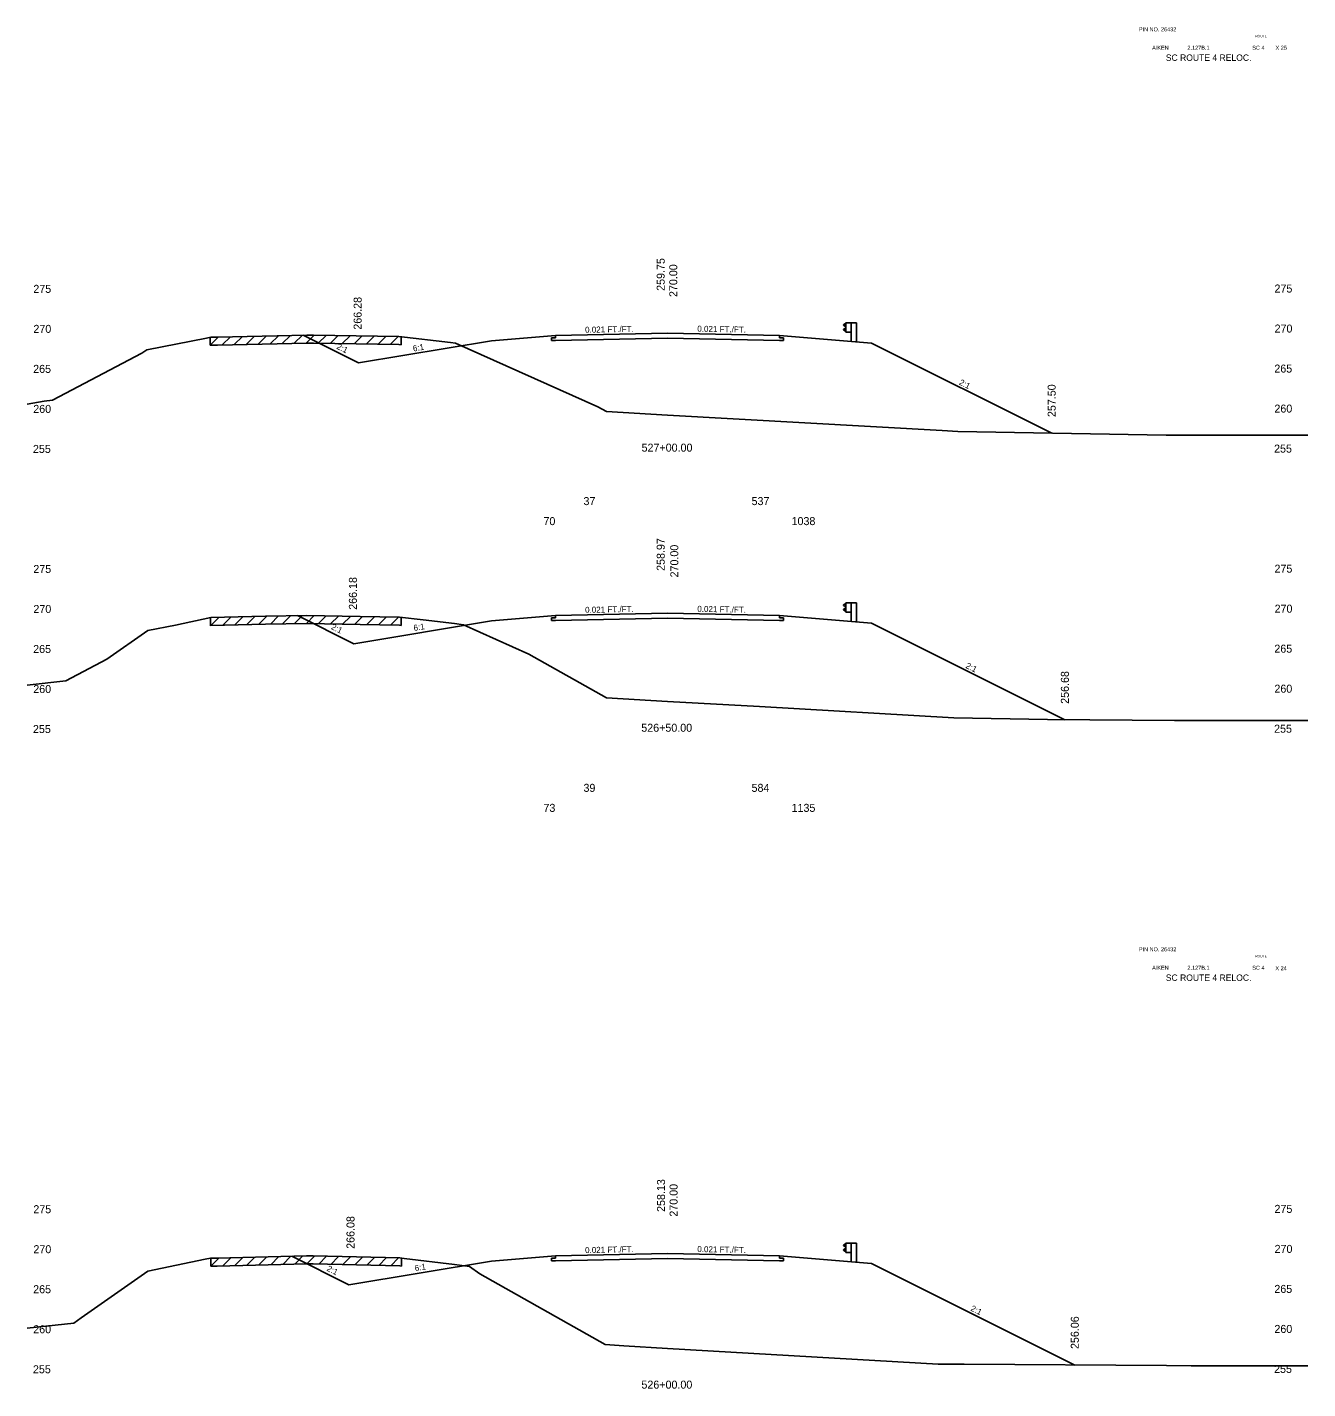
# Model space of a CAD drawing. Extents: x 2967 to 4323, y -3677 to -817.
# Drawn here: x 3188.8 to 3348.8, y -986.8 to -816.6 of the extents above; entities that cross this region are included whole.
import ezdxf

# ---------------------------------------------------------------- set-up
doc = ezdxf.new("R2010")
doc.units = 0
for name, color, linetype in [('Level 1', 7, 'Continuous'), ('Level 10', 7, 'Continuous'), ('Level 11', 7, 'Continuous'), ('Level 12', 7, 'Continuous'), ('Level 20', 7, 'Continuous'), ('Level 24', 7, 'Continuous'), ('Level 3', 7, 'Continuous'), ('Level 32', 7, 'Continuous'), ('Level 33', 7, 'Continuous'), ('Level 59', 7, 'Continuous'), ('Level 6', 7, 'Continuous'), ('Level 60', 7, 'Continuous'), ('Level 61', 7, 'Continuous'), ('Level 7', 7, 'Continuous')]:
    doc.layers.add(name, color=color, linetype=linetype)

msp = doc.modelspace()

# ---------------------------------------------------------------- linework, layer by layer
at = {"layer": 'Level 11'}
for p, q in [((3254.76, -855.43), (3254.26, -855.44)), ((3254.26, -855.44), (3254.26, -855.78)), ((3254.76, -855.13), (3254.76, -855.43)), ((3282.76, -855.43), (3282.76, -855.13)), ((3283.26, -855.44), (3282.76, -855.43)), ((3283.26, -855.78), (3283.26, -855.44)), ((3254.26, -855.78), (3254.76, -855.77)), ((3282.76, -855.77), (3283.26, -855.78)), ((3254.76, -890.43), (3254.26, -890.44)), ((3254.26, -890.44), (3254.26, -890.78)), ((3254.26, -890.78), (3254.76, -890.77)), ((3254.76, -890.13), (3254.76, -890.43)), ((3282.76, -890.43), (3282.76, -890.13)), ((3283.26, -890.44), (3282.76, -890.43)), ((3282.76, -890.77), (3283.26, -890.78)), ((3283.26, -890.78), (3283.26, -890.44)), ((3254.76, -970.43), (3254.26, -970.44)), ((3254.26, -970.44), (3254.26, -970.78)), ((3254.26, -970.78), (3254.76, -970.77)), ((3254.76, -970.13), (3254.76, -970.43)), ((3282.76, -970.43), (3282.76, -970.13)), ((3283.26, -970.44), (3282.76, -970.43)), ((3282.76, -970.77), (3283.26, -970.78)), ((3283.26, -970.78), (3283.26, -970.44))]:
    msp.add_line(p, q, dxfattribs=at)
at = {"layer": 'Level 12'}
for p, q in [((3268.76, -855.48), (3254.76, -855.77)), ((3282.76, -855.77), (3268.76, -855.48)), ((3268.76, -890.48), (3254.76, -890.77)), ((3282.76, -890.77), (3268.76, -890.48)), ((3268.76, -970.48), (3254.76, -970.77)), ((3282.76, -970.77), (3268.76, -970.48))]:
    msp.add_line(p, q, dxfattribs=at)
at = {"layer": 'Level 24'}
for p, q in [((3291.03, -853.62), (3290.76, -853.82)), ((3290.76, -853.82), (3290.76, -853.87)), ((3290.76, -853.87), (3291.03, -854.07)), ((3291.03, -854.72), (3291.03, -853.55)), ((3291.03, -853.55), (3291.7, -853.55)), ((3291.7, -853.55), (3291.7, -855.88)), ((3291.7, -853.55), (3292.36, -853.55)), ((3292.36, -853.55), (3292.36, -855.93)), ((3290.76, -854.39), (3291.03, -854.19)), ((3290.76, -854.44), (3290.76, -854.39)), ((3291.03, -854.64), (3290.76, -854.44)), ((3291.03, -854.72), (3291.7, -854.72)), ((3291.03, -888.62), (3290.76, -888.82)), ((3290.76, -888.82), (3290.76, -888.87)), ((3290.76, -888.87), (3291.03, -889.07)), ((3290.76, -889.39), (3291.03, -889.19)), ((3290.76, -889.44), (3290.76, -889.39)), ((3291.03, -889.64), (3290.76, -889.44)), ((3291.03, -889.72), (3291.03, -888.55)), ((3291.03, -888.55), (3291.7, -888.55)), ((3291.03, -889.72), (3291.7, -889.72)), ((3291.7, -888.55), (3291.7, -890.88)), ((3291.7, -888.55), (3292.36, -888.55)), ((3292.36, -888.55), (3292.36, -890.93)), ((3291.03, -968.62), (3290.76, -968.82)), ((3290.76, -968.82), (3290.76, -968.87)), ((3290.76, -968.87), (3291.03, -969.07)), ((3290.76, -969.39), (3291.03, -969.19)), ((3290.76, -969.44), (3290.76, -969.39)), ((3291.03, -969.64), (3290.76, -969.44)), ((3291.03, -969.72), (3291.03, -968.55)), ((3291.03, -968.55), (3291.7, -968.55)), ((3291.03, -969.72), (3291.7, -969.72)), ((3291.7, -968.55), (3291.7, -970.88)), ((3291.7, -968.55), (3292.36, -968.55)), ((3292.36, -968.55), (3292.36, -970.93))]:
    msp.add_line(p, q, dxfattribs=at)
at = {"layer": 'Level 59'}
for p, q in [((3254.76, -855.13), (3268.76, -854.84)), ((3268.76, -854.84), (3282.76, -855.13)), ((3254.76, -890.13), (3268.76, -889.84)), ((3268.76, -889.84), (3282.76, -890.13)), ((3254.76, -970.13), (3268.76, -969.84)), ((3268.76, -969.84), (3282.76, -970.13))]:
    msp.add_line(p, q, dxfattribs=at)
at = {"layer": 'Level 6'}
for p, q in [((3246.76, -855.8), (3254.76, -855.13)), ((3282.76, -855.13), (3290.76, -855.8)), ((3290.76, -855.8), (3294.26, -856.09)), ((3246.76, -890.8), (3254.76, -890.13)), ((3282.76, -890.13), (3290.76, -890.8)), ((3290.76, -890.8), (3294.26, -891.09)), ((3246.76, -970.8), (3254.76, -970.13)), ((3282.76, -970.13), (3290.76, -970.8)), ((3290.76, -970.8), (3294.26, -971.09))]:
    msp.add_line(p, q, dxfattribs=at)
at = {"layer": 'Level 60'}
for p, q in [((3203.69, -856.93), (3211.15, -855.47)), ((3211.15, -855.47), (3211.69, -855.36)), ((3211.69, -855.36), (3212.52, -855.34)), ((3212.52, -855.34), (3223.69, -855.09)), ((3223.69, -855.09), (3224.52, -855.1)), ((3224.52, -855.1), (3235.19, -855.28)), ((3235.19, -855.28), (3241.66, -856.02)), ((3191.9, -863.23), (3203.07, -857.37)), ((3203.07, -857.37), (3203.69, -856.93)), ((3241.66, -856.02), (3242.27, -856.09)), ((3242.27, -856.09), (3260.06, -864.06)), ((3188.76, -863.71), (3190.86, -863.35)), ((3190.86, -863.35), (3191.9, -863.23)), ((3260.06, -864.06), (3261.12, -864.66)), ((3261.12, -864.66), (3268.76, -865.09)), ((3268.76, -865.09), (3303.06, -867.02)), ((3303.06, -867.02), (3305.04, -867.13)), ((3305.04, -867.13), (3331.06, -867.6)), ((3331.06, -867.6), (3332.07, -867.61)), ((3332.07, -867.61), (3332.8, -867.61)), ((3332.8, -867.61), (3348.76, -867.6)), ((3203.84, -892), (3207.28, -891.33)), ((3207.28, -891.33), (3211.68, -890.4)), ((3211.68, -890.4), (3218.51, -890.23)), ((3218.51, -890.23), (3223.66, -890.12)), ((3223.66, -890.12), (3230.36, -890.27)), ((3230.36, -890.27), (3235.26, -890.35)), ((3235.26, -890.35), (3238.23, -890.68)), ((3238.23, -890.68), (3242.13, -891.14)), ((3242.13, -891.14), (3243.27, -891.31)), ((3243.27, -891.31), (3251.43, -894.97)), ((3198.69, -895.61), (3203.84, -892)), ((3193.57, -898.3), (3198.69, -895.61)), ((3251.43, -894.97), (3261.12, -900.44)), ((3188.76, -898.85), (3193.57, -898.3)), ((3261.12, -900.44), (3268.76, -900.87)), ((3268.76, -900.87), (3280.25, -901.52)), ((3280.25, -901.52), (3304.53, -902.94)), ((3304.53, -902.94), (3316.25, -903.15)), ((3316.25, -903.15), (3332.09, -903.27)), ((3332.09, -903.27), (3343.53, -903.27)), ((3343.53, -903.27), (3348.76, -903.27)), ((3203.82, -972.08), (3211.01, -970.57)), ((3211.01, -970.57), (3211.67, -970.44)), ((3211.67, -970.44), (3212.49, -970.42)), ((3212.49, -970.42), (3223.65, -970.14)), ((3223.65, -970.14), (3224.47, -970.16)), ((3224.47, -970.16), (3235.32, -970.41)), ((3235.32, -970.41), (3235.86, -970.48)), ((3235.86, -970.48), (3242.16, -971.22)), ((3242.16, -971.22), (3244.01, -971.5)), ((3195.51, -977.91), (3203.82, -972.08)), ((3244.01, -971.5), (3245.32, -972.38)), ((3245.32, -972.38), (3260.99, -981.24)), ((3194.6, -978.54), (3195.51, -977.91)), ((3188.76, -979.2), (3194.6, -978.54)), ((3260.99, -981.24), (3263.31, -981.39)), ((3263.31, -981.39), (3268.76, -981.71)), ((3268.76, -981.71), (3302.58, -983.69)), ((3302.58, -983.69), (3305.84, -983.68)), ((3305.84, -983.68), (3331.12, -983.87)), ((3331.12, -983.87), (3334.19, -983.89)), ((3334.19, -983.89), (3348.76, -983.89))]:
    msp.add_line(p, q, dxfattribs=at)
at = {"layer": 'Level 61'}
for p, q in [((3212.65, -855.33), (3211.61, -856.37)), ((3211.61, -855.37), (3211.61, -856.37)), ((3214.14, -855.3), (3213.11, -856.32)), ((3215.64, -855.27), (3214.61, -856.29)), ((3217.14, -855.23), (3216.11, -856.26)), ((3218.64, -855.2), (3217.61, -856.22)), ((3220.14, -855.17), (3219.11, -856.19)), ((3221.64, -855.13), (3220.61, -856.16)), ((3223.14, -855.1), (3222.11, -856.12)), ((3224.59, -855.11), (3223.61, -856.09)), ((3226.1, -855.13), (3225.11, -856.11)), ((3227.6, -855.16), (3226.61, -856.14)), ((3229.1, -855.18), (3228.11, -856.16)), ((3230.6, -855.21), (3229.61, -856.19)), ((3232.1, -855.23), (3231.11, -856.21)), ((3233.6, -855.25), (3232.61, -856.24)), ((3235.1, -855.28), (3234.11, -856.26)), ((3235.46, -856.31), (3235.46, -855.31)), ((3211.61, -856.37), (3211.69, -856.36)), ((3211.69, -856.36), (3212.52, -856.34)), ((3212.52, -856.34), (3223.69, -856.09)), ((3223.69, -856.09), (3224.52, -856.1)), ((3224.52, -856.1), (3235.19, -856.28)), ((3235.19, -856.28), (3235.46, -856.31)), ((3212.68, -890.38), (3211.65, -891.41)), ((3211.65, -890.41), (3211.65, -891.41)), ((3211.65, -891.41), (3211.68, -891.4)), ((3211.68, -891.4), (3218.51, -891.23)), ((3214.18, -890.34), (3213.15, -891.37)), ((3215.68, -890.3), (3214.65, -891.33)), ((3217.18, -890.27), (3216.15, -891.29)), ((3218.68, -890.23), (3217.65, -891.25)), ((3218.51, -891.23), (3223.66, -891.12)), ((3220.17, -890.19), (3219.15, -891.22)), ((3221.67, -890.16), (3220.65, -891.18)), ((3223.17, -890.13), (3222.15, -891.15)), ((3224.63, -890.14), (3223.65, -891.12)), ((3223.66, -891.12), (3230.36, -891.27)), ((3226.13, -890.17), (3225.15, -891.15)), ((3227.63, -890.2), (3226.65, -891.18)), ((3229.13, -890.24), (3228.15, -891.22)), ((3230.63, -890.27), (3229.65, -891.25)), ((3230.36, -891.27), (3235.26, -891.35)), ((3232.13, -890.29), (3231.15, -891.28)), ((3233.63, -890.32), (3232.65, -891.3)), ((3235.13, -890.34), (3234.15, -891.33)), ((3235.26, -891.35), (3235.5, -891.37)), ((3235.5, -891.37), (3235.5, -890.37)), ((3212.71, -970.42), (3211.69, -971.44)), ((3211.69, -970.44), (3211.69, -971.44)), ((3211.69, -971.44), (3212.49, -971.42)), ((3212.49, -971.42), (3223.65, -971.14)), ((3214.21, -970.38), (3213.19, -971.41)), ((3215.71, -970.34), (3214.69, -971.37)), ((3217.21, -970.31), (3216.19, -971.33)), ((3218.71, -970.27), (3217.69, -971.29)), ((3220.21, -970.23), (3219.19, -971.26)), ((3221.71, -970.19), (3220.69, -971.22)), ((3223.21, -970.15), (3222.19, -971.18)), ((3223.65, -971.14), (3224.47, -971.16)), ((3224.66, -970.17), (3223.69, -971.14)), ((3224.47, -971.16), (3235.32, -971.41)), ((3226.16, -970.2), (3225.19, -971.18)), ((3227.66, -970.24), (3226.69, -971.21)), ((3229.16, -970.27), (3228.19, -971.25)), ((3230.66, -970.3), (3229.69, -971.28)), ((3232.16, -970.34), (3231.19, -971.31)), ((3233.66, -970.37), (3232.69, -971.35)), ((3235.16, -970.4), (3234.19, -971.38)), ((3235.32, -971.41), (3235.53, -971.44)), ((3235.53, -971.44), (3235.53, -970.44))]:
    msp.add_line(p, q, dxfattribs=at)
at = {"layer": 'Level 7'}
for p, q in [((3223.22, -855.1), (3230.16, -858.57)), ((3230.16, -858.57), (3246.76, -855.8)), ((3294.26, -856.09), (3316.76, -867.34)), ((3222.51, -890.14), (3229.56, -893.67)), ((3229.56, -893.67), (3246.76, -890.8)), ((3294.26, -891.09), (3318.41, -903.17)), ((3221.81, -970.19), (3228.96, -973.77)), ((3228.96, -973.77), (3246.76, -970.8)), ((3294.26, -971.09), (3319.65, -983.79))]:
    msp.add_line(p, q, dxfattribs=at)

# ---------------------------------------------------------------- texts
at = {"layer": 'Level 1'}
for s, p in [('37', (3258.26, -876.34)), ('537', (3279.26, -876.34)), ('70', (3253.26, -878.84)), ('1038', (3284.26, -878.84)), ('39', (3258.26, -912.17)), ('584', (3279.26, -912.17)), ('73', (3253.26, -914.67)), ('1135', (3284.26, -914.67))]:
    msp.add_text(s, height=1, dxfattribs=at).set_placement(p)
at = {"layer": 'Level 10'}
for s, p in [('259.75', (3268.41, -849.57)), ('258.97', (3268.41, -884.56)), ('258.13', (3268.45, -964.66))]:
    msp.add_text(s, height=1, rotation=90, dxfattribs=at).set_placement(p)
for s, p in [('527+00.00', (3265.52, -869.66)), ('526+50.00', (3265.48, -904.66)), ('526+00.00', (3265.5, -986.74))]:
    msp.add_text(s, height=1, dxfattribs=at).set_placement(p)
at = {"layer": 'Level 20'}
for s, height, p in [('PIN NO. 26432', 0.5, (3327.65, -817.14)), ('ROUTE', 0.3, (3342.19, -817.88)), ('AIKEN', 0.5, (3329.31, -819.44)), ('SC ROUTE 4 RELOC.', 0.8, (3331.02, -820.83)), (' 2.127B.1', 0.5, (3333.53, -819.44)), ('SC 4', 0.5, (3341.82, -819.44)), ('X 25', 0.5, (3344.73, -819.44)), ('PIN NO. 26432', 0.5, (3327.65, -932.09)), ('AIKEN', 0.5, (3329.31, -934.4)), (' 2.127B.1', 0.5, (3333.53, -934.4)), ('SC 4', 0.5, (3341.82, -934.4)), ('ROUTE', 0.3, (3342.19, -932.84)), ('X 24', 0.5, (3344.71, -934.46)), ('SC ROUTE 4 RELOC.', 0.8, (3331.02, -935.79))]:
    msp.add_text(s, height=height, dxfattribs=at).set_placement(p)
at = {"layer": 'Level 3'}
for s, p in [(' 275', (3189.15, -849.82)), (' 275', (3344.23, -849.78)), (' 270', (3189.16, -854.82)), (' 270', (3344.24, -854.78)), (' 265', (3189.13, -859.82)), (' 265', (3344.21, -859.78)), (' 260', (3189.14, -864.82)), (' 260', (3344.22, -864.78)), (' 255', (3189.1, -869.82)), (' 255', (3344.18, -869.78)), (' 275', (3189.15, -884.82)), (' 275', (3344.23, -884.78)), (' 270', (3189.16, -889.82)), (' 270', (3344.24, -889.78)), (' 265', (3189.13, -894.82)), (' 265', (3344.21, -894.78)), (' 260', (3189.14, -899.82)), (' 260', (3344.22, -899.78)), (' 255', (3189.1, -904.82)), (' 255', (3344.18, -904.78)), (' 275', (3189.15, -964.82)), (' 275', (3344.23, -964.78)), (' 270', (3189.16, -969.82)), (' 270', (3344.24, -969.78)), (' 265', (3189.13, -974.82)), (' 265', (3344.21, -974.78)), (' 260', (3189.14, -979.82)), (' 260', (3344.22, -979.78)), (' 255', (3189.1, -984.82)), (' 255', (3344.18, -984.78))]:
    msp.add_text(s, height=1, dxfattribs=at).set_placement(p)
at = {"layer": 'Level 32'}
for s, rotation, p in [('0.021 FT./FT.', 1.1916, (3258.47, -854.81)), ('0.021 FT./FT.', 358.8084, (3272.48, -854.67)), ('2:1', 333.435, (3227.34, -856.77)), ('6:1', 9.4623, (3237.01, -857.15)), ('2:1', 333.435, (3305.12, -861.24)), ('0.021 FT./FT.', 1.1916, (3258.47, -889.81)), ('0.021 FT./FT.', 358.8084, (3272.48, -889.67)), ('2:1', 333.435, (3226.66, -891.8)), ('6:1', 9.4623, (3237.09, -892.07)), ('2:1', 333.435, (3305.94, -896.65)), ('0.021 FT./FT.', 1.1916, (3258.47, -969.81)), ('0.021 FT./FT.', 358.8084, (3272.48, -969.67)), ('2:1', 333.435, (3226.11, -971.97)), ('6:1', 9.4623, (3237.24, -972.07)), ('2:1', 333.435, (3306.56, -976.96))]:
    msp.add_text(s, height=0.75, rotation=rotation, dxfattribs=at).set_placement(p)
at = {"layer": 'Level 33'}
for s, p in [('266.28', (3230.54, -854.42)), ('257.50', (3317.26, -865.34)), ('266.18', (3229.95, -889.42)), ('256.68', (3318.91, -901.17)), ('266.08', (3229.65, -969.27)), ('256.06', (3320.15, -981.79))]:
    msp.add_text(s, height=1, rotation=90, dxfattribs=at).set_placement(p)
at = {"layer": 'Level 59'}
for p in [(3269.98, -850.71), (3270.11, -885.75), (3270.02, -965.62)]:
    msp.add_text(' 270.00', height=1, rotation=90, dxfattribs=at).set_placement(p)

doc.saveas('drawing.dxf')
